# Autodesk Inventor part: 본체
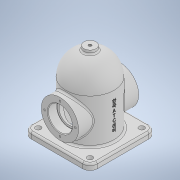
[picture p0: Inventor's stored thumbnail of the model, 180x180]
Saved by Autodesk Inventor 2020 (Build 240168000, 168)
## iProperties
Created: 2021-07
Part Number: 본체
Material: 일반
Document SubType Name: Modeling
Designer: Owner
Density: 1 g/cm^3
Appearance: 기본값
Mass: 320.734 g
Surface Area: 800.675 cm^2
Volume: 320.734 cm^3
Author: Owner
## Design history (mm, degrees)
sketch "스케치1"
  geometry: C1 r 40 at (0, 0); 1 further point
  constraints: 1 centre point, 1 coincident
  dimensions: "d0" = 80 diameter of C1
extrude "돌출1" new body sketch "스케치1" distance "d1" = 124; taper "d2" = 0 deg
fillet "모깎기1" dims "d3" = 40
feature "쉘1" dims "d4" = 8
sketch "스케치2"
  geometry: L1 (-55, -55)-(55, -55); L2 (55, -55)-(55, 55); L3 (55, 55)-(-55, 55); L4 (-55, 55)-(-55, -55); L5 (-55, -55)-(55, 55); L6 (55, -55)-(-55, 55); C1 r 40 at (0, 0) reference; C2 r 32 at (0, 0) reference; C3 r 32 at (0, 0) reference; C4 r 40 at (0, 0) reference; 1 further point
  constraints: 12 end point, 2 midpoint, 2 parallel, 1 horizontal, 1 perpendicular
  dimensions: "d5" = 110 distance of L3.end L2.end; "d6" = 110 distance of L2.end L1.end
extrude "돌출2" join sketch "스케치2" distance "d7" = 10; taper "d8" = 0 deg
node "작업 평면4"
sketch "스케치4"
  geometry: L1 (55, 0)-(-55, 0) reference; C1 r 31 at (0, 48); 1 further point
  constraints: 1 centre point
  dimensions: "d15" = 62 diameter of C1; "d16" = 48 distance from line of C1.centre L1
extrude "돌출4" join sketch "스케치4" stored distance "d17" = 124; taper "d18" = 0 deg
sketch "스케치5"
  geometry: C1 r 31 at (0, 0) reference; 2 further points
  constraints: 1 coincident
hole "구멍1" sketch "스케치5" at (0, 0) diameter "d19" = 33; stored, may be unused: countersink angle "d23" = 90 deg, drill point angle "d25" = 0 deg; dims "d20" = 9, "d21" = 40, "d22" = 15, "d24" = 11
sketch "스케치6"
  geometry: C1 r 20 at (0, 0) reference; C2 r 31 at (0, 0) reference; 2 further points
  dimensions: "d26" = 25.5 distance of point (0, 25.5) C1.centre
hole "구멍2" sketch "스케치6" at (0, 25.5) diameter "d27" = 3.242; stored, may be unused: countersink angle "d31" = 90 deg, drill point angle "d33" = 118 deg; dims "d28" = 8, "d29" = 40, "d30" = 15, "d32" = 10
fillet "모깎기2" dims "d37" = 3
chamfer "모따기1" distance "d38" = 1; stored, may be unused: second distance "d39" = 2, angle "d40" = 45 deg
fillet "모깎기3" dims "d41" = 0.3
node "작업 평면5"
sketch "스케치7"
  geometry: C1 r 10 at (0, 0); 1 further point
  constraints: 1 centre point, 1 coincident
  dimensions: "d43" = 20 diameter of C1
extrude "돌출5" join sketch "스케치7" stored distance "d44" = 124; taper "d45" = 0 deg
sketch "스케치8"
  geometry: C1 r 10 at (0, 0) reference; 2 further points
  constraints: 1 coincident
hole "구멍3" sketch "스케치8" at (0, 0) diameter "d46" = 4.917; stored, may be unused: countersink angle "d50" = 90 deg, drill point angle "d52" = 118 deg; dims "d47" = 12, "d48" = 40, "d49" = 15, "d51" = 17.1
fillet "모깎기4" dims "d53" = 3
fillet "모깎기5" dims "d54" = 3
fillet "모깎기6" dims "d55" = 12
sketch "스케치10"
  geometry: A1 r 12 centre (-43, -43) between (-55, -43) and (-43, -55) reference; 2 further points
  constraints: 1 coincident
hole "구멍4" sketch "스케치10" at (-43, -43) diameter "d56" = 9; stored, may be unused: countersink angle "d60" = 90 deg, drill point angle "d62" = 118 deg; dims "d57" = 12, "d58" = 40, "d59" = 15, "d61" = 17.1
node "작업 평면6"
sketch "스케치11"
  geometry: L1 (0, -43)-(0, 43) reference; 3 further points
  constraints: 1 horizontal alignment, 1 midpoint, 1 other
  dimensions: "d69" = 48 distance from line of L1 point (48, 0)
feature "엠보싱1" sketch "스케치11" dims "d1" = 124, "d2" = 0, "d7" = 10, "d8" = 0, "d66" = 0.5, "d67" = 0
fillet "모깎기7" dims "d68" = 3
node "솔리드1"
pattern_circular "원형 패턴1" dims angle "d35" = 360 deg
mirror "미러1"
pattern_circular "원형 패턴2" dims angle "d64" = 360 deg
node "투영된 루프1"
node "투영된 루프2"
feature "A9D066F2-1C7D-4E18-AEED-F7BC21143FA4" dims "d19" = 33, "d20" = 9, "d21" = 40, "d22" = 15, "d23" = 90 deg, "d24" = 11, "d25" = 0
other parameters: "d42" = -129
